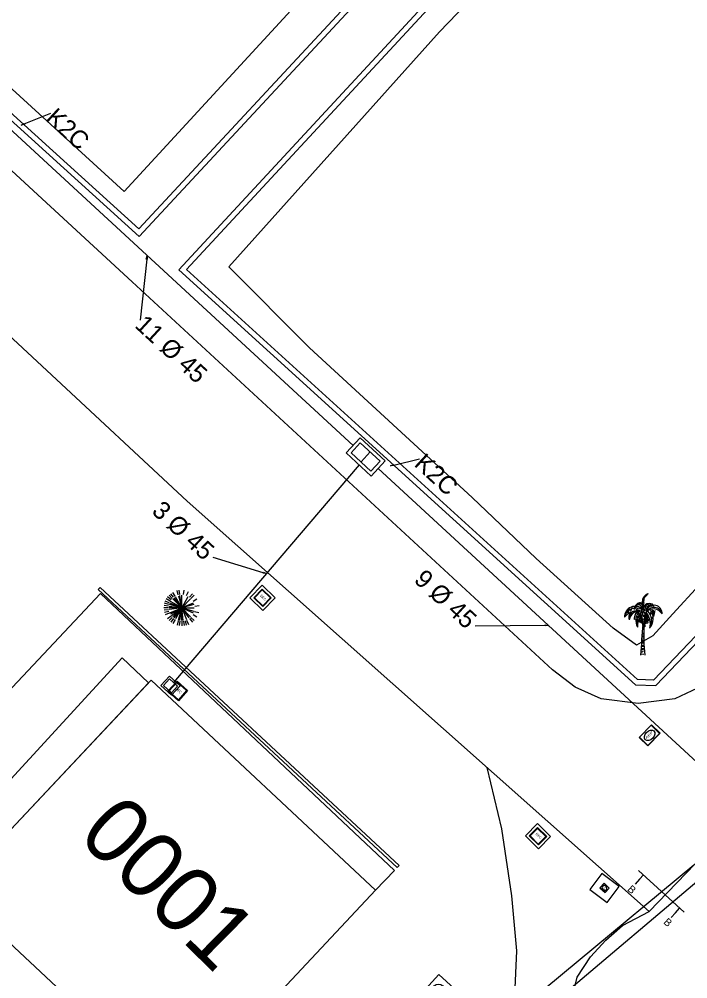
# Model space of a CAD drawing. Extents: x 343997 to 344255, y 298512 to 298767.
# Drawn here: x 344085.4 to 344122.6, y 298618.2 to 298671.5 of the extents above; entities that cross this region are included whole.
import ezdxf

# ---------------------------------------------------------------- set-up
doc = ezdxf.new("R2010")
doc.units = 0
for name, color, linetype in [('Default', 7, 'Continuous'), ('DH_CADRE-CARTOUCHE', 7, 'Continuous'), ('DH_TEXTE', 7, 'Continuous'), ('DIR-Projet VRD1', 7, 'Continuous'), ('EDE - coupe BT', 7, 'Continuous'), ('EDE - VRD - O-DONNEE', 7, 'Continuous'), ('GO_DALLE', 7, 'Continuous'), ('GO_MUR', 7, 'Continuous'), ('O-Projet New VRD', 7, 'Continuous'), ('OPT texte', 7, 'Continuous'), ('OPT VRD', 7, 'Continuous'), ('PC_REBAR', 7, 'Continuous'), ('PS_MID', 7, 'Continuous'), ('PS_PLATE', 7, 'Continuous'), ('RES_EAU', 7, 'Continuous'), ('RES_ELECTRICITE', 7, 'Continuous')]:
    doc.layers.add(name, color=color, linetype=linetype)

# ---------------------------------------------------------------- blocks, each defined once
blk = doc.blocks.new('RES_EAU')
at = {"layer": 'RES_EAU'}
for points in [[(0, 0), (0, 0.1), (0.1, 0.1), (0.1, 0)], [(0.0025, 0.0025), (0.0025, 0.0975), (0.0975, 0.0975), (0.0975, 0.0025)]]:
    blk.add_lwpolyline(points, close=True, dxfattribs=at)
blk.add_circle((0.05, 0.05), 0.035, dxfattribs=at)
blk.add_text('AEP', height=0.02, dxfattribs=at).set_placement((0.0224, 0.0448))
blk = doc.blocks.new('RES_ELECTRICITE')
at = {"layer": 'RES_ELECTRICITE'}
for points in [[(0, 0), (0, 0.1), (0.1, 0.1), (0.1, 0)], [(0.005, 0.005), (0.005, 0.095), (0.095, 0.095), (0.095, 0.005)]]:
    blk.add_lwpolyline(points, close=True, dxfattribs=at)
blk.add_text('EEC', height=0.02, dxfattribs=at).set_placement((0.0237, 0.046))
blk = doc.blocks.new('COCO')
at = {"layer": 'Default'}
for p, q in [((-0.0037, 0.106), (0.0056, 0.1071)), ((0.0058, 0.114), (-0.003, 0.1162)), ((-0.0026, 0.1226), (0.0061, 0.1212)), ((-0.0062, 0.0537), (0.0046, 0.0552)), ((0.0047, 0.0655), (-0.0058, 0.0642)), ((-0.0046, 0.0891), (0.0052, 0.0927)), ((0.0054, 0.0998), (-0.0041, 0.0985)), ((0.0046, 0.0033), (-0.0076, 0.0051)), ((-0.0073, 0.017), (0.0045, 0.0209)), ((0.0045, 0.0292), (-0.007, 0.0288)), ((-0.0068, 0.0371), (0.0045, 0.0374)), ((0.0045, 0.047), (-0.0065, 0.0453))]:
    blk.add_line(p, q, dxfattribs=at)
for points in [[(0.0029, 0.2551), (-0.0016, 0.2896), (0.0002, 0.3125), (0.0059, 0.3241), (0.0173, 0.3348), (0.0189, 0.3356), (0.0282, 0.3415), (0.0266, 0.3373), (0.02, 0.3318), (0.0143, 0.3247), (0.0093, 0.32), (0.0081, 0.3165), (0.0057, 0.3133), (0.0057, 0.3099), (0.006, 0.3037), (0.0039, 0.2989), (0.0039, 0.2944), (0.0049, 0.2877), (0.0037, 0.2841), (0.0013, 0.2736)], [(-0.0487, 0.268), (-0.0386, 0.265)], [(0.0013, 0.2736), (0.0036, 0.2813), (0.0046, 0.2746)], [(0.0196, 0.2687), (0.0323, 0.2715)], [(0.0283, 0.2765), (0.0331, 0.2786)], [(-0.0746, 0.2559), (-0.0864, 0.2483)], [(-0.077, 0.2413), (-0.0836, 0.2333)], [(-0.0607, 0.2534), (-0.0704, 0.2443)], [(-0.0636, 0.2639), (-0.0541, 0.2608)], [(-0.0421, 0.258), (-0.0503, 0.2523)], [(-0.0183, 0.2493), (-0.0348, 0.2417), (-0.0401, 0.2307), (-0.0448, 0.2203), (-0.0471, 0.2086), (-0.0474, 0.2023), (-0.0466, 0.1973), (-0.0455, 0.2054), (-0.0451, 0.2146), (-0.0387, 0.2292), (-0.0351, 0.2354), (-0.0284, 0.2404), (-0.0233, 0.2445), (-0.0012, 0.2495)], [(-0.0256, 0.2553), (-0.0385, 0.2508)], [(-0.0276, 0.2151), (-0.0329, 0.2086)], [(-0.0203, 0.2314), (-0.0274, 0.2258)], [(-0.023, 0.2152), (-0.0237, 0.2043)], [(-0.0161, 0.2218), (-0.0158, 0.2122)], [(-0.004, 0.2247), (-0.0081, 0.2179)], [(0.0015, 0.2414), (-0.0056, 0.2352)], [(0.0022, 0.224), (0.0043, 0.213)], [(0.0081, 0.2404), (0.0106, 0.2299)], [(0.0133, 0.2608), (0.0185, 0.2634)], [(0.0385, 0.237), (0.0469, 0.2254)], [(-0.0321, 0.1997), (-0.0364, 0.19)], [(-0.0059, 0.2024), (-0.0083, 0.1998)], [(-0.0025, 0.2032), (0.0002, 0.1954)], [(0.0473, 0.2115), (0.0509, 0.2012)], [(-0.0055, 0.0716), (0.0048, 0.0717), (0.0049, 0.0787), (-0.0051, 0.0795)]]:
    blk.add_lwpolyline(points, dxfattribs=at)
for centre, radius in [((-0.0187, 0.1897), 0.00384), ((-0.0144, 0.1978), 0.00616), ((-0.0124, 0.1896), 0.00376), ((-0.011, 0.184), 0.00471), ((0.0134, 0.1862), 0.00549), ((0.0208, 0.1822), 0.00626), ((0.0254, 0.1938), 0.00628)]:
    blk.add_circle(centre, radius, dxfattribs=at)
for centre, radius, start, end in [((-0.0427, 0.2113), 0.0595, 43.6121, 181.4625), ((-0.0123, 0.259), 0.0323, 122.3475, 158.7636), ((-0.0199, 0.2618), 0.0238, 4.5218, 154.101), ((-0.0252, 0.2556), 0.0231, 4.2441, 134.2103), ((-0.016, 0.2647), 0.0255, 21.0861, 122.3475), ((0.0376, 0.2508), 0.0372, 113.7681, 175.3309), ((0.0376, 0.2508), 0.0372, 113.7681, 175.3309), ((0.0418, 0.2527), 0.0326, 97.1248, 183.9512), ((0.1025, 0.2053), 0.0958, 126.6858, 153.1664), ((0.0618, 0.2316), 0.0451, 356.1627, 159.0009), ((0.0344, 0.2407), 0.0451, 69.0817, 104.862), ((-0.1005, 0.1577), 0.1786, 37.5668, 40.5156), ((-0.0254, 0.228), 0.0869, 28.4725, 37.0965), ((0.0493, 0.2767), 0.00679, 35.3205, 126.6858), ((-0.0054, 0.2379), 0.0738, 25.8194, 35.3205), ((-0.0291, 0.1543), 0.0918, 76.7389, 142.8025), ((-0.038, 0.1964), 0.0648, 57.9192, 166.6201), ((-0.03, 0.212), 0.0482, 151.1331, 199.5942), ((-0.0196, 0.1874), 0.0565, 78.514, 171.3504), ((-0.032, 0.2055), 0.0433, 119.0834, 188.7621), ((0.0362, 0.1922), 0.0754, 136.7113, 208.8221), ((0.0551, 0.179), 0.0879, 137.733, 194.3716), ((0.0649, 0.1599), 0.0949, 145.5146, 182.4528), ((0.062, 0.2159), 0.0753, 153.0868, 230.1124), ((0.0659, 0.2068), 0.0718, 142.3554, 222.2794), ((-0.0007, 0.2465), 0.00563, 81.7475, 144.3035), ((-0.0189, 0.121), 0.1324, 71.3715, 81.7475), ((0.0294, 0.2595), 0.0256, 198.6765, 199.7627), ((0.0963, 0.1939), 0.09, 143.9866, 203.4288), ((0.0544, 0.1816), 0.0474, 137.1953, 172.8987), ((0.0308, 0.2014), 0.0226, 121.4297, 182.29), ((2.7302, 0.0106), 2.7266, 175.4791, 176.5597), ((0.0311, 0.2152), 0.0219, 141.856, 191.5175), ((0.0404, 0.1878), 0.0354, 125.0585, 146.3893), ((0.0398, 0.2098), 0.0301, 136.4569, 162.0685), ((0.0357, 0.2084), 0.0244, 133.1184, 172.7534), ((-0.0759, 0.1958), 0.0922, 344.8505, 15.8988), ((-0.0404, 0.2045), 0.0619, 329.4666, 26.6793), ((-0.0289, 0.211), 0.0564, 317.8279, 12.3386), ((0.059, 0.2015), 0.0548, 29.5654, 139.3517), ((-0.0543, 0.1744), 0.096, 344.8781, 41.1461), ((-0.0341, 0.19), 0.0828, 46.9767, 50.1231), ((0.0609, 0.2187), 0.0468, 12.1077, 148.3146), ((-0.0157, 0.2027), 0.074, 51.2475, 54.5217), ((-0.0341, 0.19), 0.0828, 334.0687, 41.194), ((-0.0157, 0.2027), 0.074, 315.1472, 39.0239), ((-0.1704, 0.1849), 0.2327, 7.5978, 16.3666), ((-0.0254, 0.228), 0.0869, 350.8883, 14.7063), ((-0.0482, 0.2552), 0.1161, 339.3597, 356.5925), ((-8.5428, 0.7294), 8.5622, 355.11326, 356.26352), ((-0.0279, 0.1637), 0.0281, 2.1499, 36.6325), ((-0.0265, 0.1505), 0.0316, 339.9997, 25.7228), ((0.0199, 0.166), 0.0176, 166.9443, 185.5966), ((0.0372, 0.1847), 0.0277, 133.5956, 173.487), ((0.0808, 0.1542), 0.0777, 142.2358, 156.28), ((0.0242, 0.1964), 0.0147, 110.9727, 165.9756)]:
    blk.add_arc(centre, radius, start, end, dxfattribs=at)
blk.add_ellipse((2.7425, 0.0272), major_axis=(-2.7371, 0.0966), ratio=0.529859, start_param=6.255729, end_param=6.369141, dxfattribs=at)
blk = doc.blocks.new('ARB2')
at = {"layer": 'Default'}
for p, q in [((-0.0575, 0.0453), (-0.0775, 0.0605)), ((-0.0513, 0.0525), (-0.0688, 0.0702)), ((-0.0438, 0.0589), (-0.0588, 0.0786)), ((-0.0356, 0.0642), (-0.0481, 0.0858)), ((-0.0181, 0.0716), (-0.0244, 0.0956)), ((-0.0088, 0.0736), (-0.0119, 0.0983)), ((0.0106, 0.0736), (0.0144, 0.0983)), ((0.0287, 0.0684), (0.0388, 0.0914)), ((0.0456, 0.0589), (0.0612, 0.0786)), ((0.0531, 0.0525), (0.0706, 0.0702)), ((-0.0731, 0), (-0.0981, 0)), ((-0.0725, 0.01), (-0.0969, 0.0133)), ((-0.0706, 0.0195), (-0.0944, 0.0259)), ((-0.0675, 0.0286), (-0.09, 0.0381)), ((-0.0631, 0.0373), (-0.0844, 0.0497)), ((0.065, 0.0373), (0.0862, 0.0497)), ((0.0744, 0.01), (0.0987, 0.0133)), ((-0.0725, -0.01), (-0.0969, -0.0133)), ((-0.0706, -0.0195), (-0.0944, -0.0259)), ((-0.0675, -0.0287), (-0.09, -0.0383)), ((-0.0575, -0.0455), (-0.0775, -0.0605)), ((-0.0513, -0.0527), (-0.0688, -0.0702)), ((0.0531, -0.0527), (0.0706, -0.0702)), ((0.065, -0.0373), (0.0862, -0.0498)), ((0.0725, -0.0195), (0.0963, -0.0259)), ((-0.0438, -0.0591), (-0.0588, -0.0787)), ((-0.0356, -0.0644), (-0.0481, -0.0859)), ((-0.0181, -0.0717), (-0.0244, -0.0956)), ((-0.0088, -0.0737), (-0.0119, -0.0983)), ((0.0013, -0.0741), (0.0013, -0.0989)), ((0.0106, -0.0737), (0.0144, -0.0983)), ((0.02, -0.0717), (0.0263, -0.0956)), ((0.0287, -0.0686), (0.0388, -0.0916)), ((0.0456, -0.0591), (0.0612, -0.0787))]:
    blk.add_line(p, q, dxfattribs=at)
for points in [[(-0.0688, 0.0091), (0.0013, 0), (-0.0338, 0.0608)], [(-0.0419, 0.0556), (0.0013, 0), (-0.0638, 0.0269)], [(-0.0169, 0.0677), (0.0013, 0), (-0.06, 0.035)], [(0.0013, 0.0008), (0.0013, 0), (-0.0081, 0.0695)], [(0.0362, 0.0608), (0.0013, 0), (0.0013, 0.0702)], [(-0.0487, -0.0497), (0.0013, 0), (-0.0694, 0)], [(-0.0638, -0.0269), (0.0013, 0), (-0.0688, -0.0092)], [(-0.0487, 0.0495), (0.0013, 0), (-0.0669, 0.0181)], [(-0.0169, -0.0678), (0.0013, 0), (-0.06, -0.0352)], [(-0.0544, -0.0428), (0.0013, 0), (-0.0338, -0.0608)], [(-0.0081, -0.0695), (0.0013, 0), (-0.0419, -0.0558)], [(0.0013, -0.0702), (0.0013, 0), (0, 0)], [(0.0656, 0.0269), (0.0013, 0), (0.0506, 0.0495)], [(0.0688, 0.0181), (0.0013, 0), (0.0713, 0)], [(0.0438, -0.0558), (0.0013, 0), (0.0656, -0.0269)], [(0.0506, -0.0497), (0.0013, 0), (0.0688, -0.0181)], [(0.01, -0.0695), (0.0013, 0), (0.0281, -0.0648)], [(0.0019, 0), (0.0013, 0), (0.0013, -0.0009)]]:
    blk.add_lwpolyline(points, dxfattribs=at)
blk = doc.blocks.new('_U58')
at = {"layer": 'EDE - VRD - O-DONNEE'}
for points in [[(0.01067, 0.01553), (-0.01067, 0.01553), (-0.01067, 0.00632), (0.01067, 0.00632)], [(-0.01067, 0.00632), (0.01067, 0.00632), (0.01067, 0), (-0.01067, 0)]]:
    blk.add_lwpolyline(points, close=True, dxfattribs=at)
for centre in [(-0.00689, 0.01114), (-0.00013, 0.01114), (0.00664, 0.01114)]:
    blk.add_circle(centre, 0.00225, dxfattribs=at)
blk.add_text('3H4', height=0.0035, dxfattribs=at).set_placement((-0.00426, 0.00143))

msp = doc.modelspace()

# ---------------------------------------------------------------- linework, layer by layer
at = {"layer": 'DH_CADRE-CARTOUCHE'}
for points in [[(344124.372, 298692.186), (344148.812, 298670.333), (344149.478, 298669.504), (344150.054, 298668.628), (344150.475, 298667.688), (344150.721, 298667.085), (344151.432, 298665.306), (344151.673, 298664.395), (344151.676, 298663.909), (344143.5, 298656.169), (344142.683, 298655.44), (344135.602, 298647.623), (344124.992, 298635.682), (344123.722, 298634.656), (344121.833, 298633.77), (344119.792, 298633.516), (344117.727, 298633.77), (344116.3, 298634.425), (344115.03, 298635.389), (344091.665, 298656.941), (344066.817, 298679.859)], [(344079.116, 298659.278), (344094.724, 298644.749), (344120.412, 298621.951), (344137.791, 298639.981), (344144.065, 298646.663), (344154.783, 298657.656), (344157.662, 298660.576), (344158.342, 298661.39), (344163.216, 298666.766), (344163.731, 298667.308), (344164.688, 298668.072), (344165.676, 298668.545), (344166.447, 298668.825), (344167.222, 298669.059), (344168.509, 298669.289), (344169.751, 298669.392), (344170.251, 298669.414), (344170.803, 298669.375), (344172.06, 298669.227), (344173.884, 298668.877), (344175.641, 298668.318)], [(344121.252, 298590.512), (344117.022, 298602.738), (344113.246, 298614.159), (344112.944, 298617.299), (344113.043, 298619.78), (344112.777, 298622.825), (344112.214, 298626.551), (344111.396, 298629.953)], [(344124.087, 298591.493), (344119.864, 298603.699), (344116.2, 298614.781), (344116.04, 298616.133), (344116.105, 298617.106), (344116.408, 298618.318), (344117.143, 298619.443), (344117.987, 298620.373), (344118.918, 298621.174), (344120.412, 298621.951)]]:
    msp.add_lwpolyline(points, dxfattribs=at)
at = {"layer": 'DIR-Projet VRD1'}
for p, q in [((344084.823, 298665.5), (344103.948, 298647.853)), ((344104.282, 298646.765), (344093.973, 298634.686)), ((344105.347, 298646.566), (344126.33, 298627.218)), ((344126.364, 298626.406), (344111.814, 298614.103))]:
    msp.add_line(p, q, dxfattribs=at)
at = {"layer": 'EDE - coupe BT'}
for p, q in [((344119.863, 298623.745), (344120.094, 298623.996)), ((344121.863, 298621.892), (344122.095, 298622.143))]:
    msp.add_line(p, q, dxfattribs=at)
for points in [[(344122.341, 298621.916), (344119.818, 298624.238)], [(344119.863, 298623.745), (344119.62, 298623.481)], [(344121.863, 298621.892), (344121.62, 298621.627)]]:
    msp.add_lwpolyline(points, dxfattribs=at)
at = {"layer": 'GO_DALLE'}
for points in [[(344098.902, 298640.078), (344098.218, 298639.381), (344098.93, 298638.685), (344099.613, 298639.382)], [(344114.202, 298626.837), (344113.528, 298626.157), (344114.246, 298625.445), (344114.921, 298626.125)], [(344117.109, 298623.181), (344118.07, 298622.459), (344118.734, 298623.347), (344117.773, 298624.069)]]:
    msp.add_lwpolyline(points, close=True, dxfattribs=at)
msp.add_lwpolyline([(344105.192, 298623.148), (344106.258, 298624.234), (344089.907, 298639.614), (344077.802, 298626.745), (344080.101, 298624.659)], dxfattribs=at)
at = {"layer": 'GO_MUR'}
msp.add_lwpolyline([(344089.894, 298639.96), (344106.509, 298624.503), (344106.406, 298624.393), (344089.792, 298639.85)], close=True, dxfattribs=at)
at = {"layer": 'O-Projet New VRD'}
msp.add_line((344104.902, 298647.486), (344104.393, 298646.934), dxfattribs=at)
for points in [[(344085.678, 298665.713), (344087.157, 298666.304)], [(344092.482, 298658.194), (344092.118, 298654.801)], [(344106.211, 298646.756), (344107.636, 298647.107)], [(344098.955, 298640.777), (344096.165, 298641.614)], [(344114.617, 298637.849), (344110.736, 298637.803)], [(344093.746, 298635.026), (344094.333, 298634.485), (344093.859, 298633.97), (344093.27, 298634.512), (344093.744, 298635.027)], [(344093.754, 298634.888), (344094.195, 298634.482), (344093.856, 298634.113), (344093.415, 298634.52), (344093.754, 298634.888)]]:
    msp.add_lwpolyline(points, dxfattribs=at)
for points in [[(344085.69, 298665.685), (344085.511, 298665.646), (344085.667, 298665.741)], [(344092.452, 298658.197), (344092.501, 298658.373), (344092.511, 298658.191)], [(344104.338, 298648.276), (344105.736, 298646.989), (344104.957, 298646.143), (344103.559, 298647.43)], [(344104.35, 298647.994), (344105.453, 298646.978), (344104.945, 298646.426), (344103.841, 298647.442)], [(344106.218, 298646.727), (344106.036, 298646.713), (344106.204, 298646.785)], [(344098.964, 298640.806), (344099.127, 298640.725), (344098.946, 298640.748)], [(344114.617, 298637.879), (344114.797, 298637.852), (344114.618, 298637.819)]]:
    msp.add_lwpolyline(points, close=True, dxfattribs=at)
at = {"layer": 'OPT VRD'}
msp.add_lwpolyline([(344122.894, 298624.526), (344110.021, 298613.871)], dxfattribs=at)
at = {"layer": 'PC_REBAR'}
for points in [[(344115.386, 298697.034), (344095.685, 298715.142), (344067.379, 298684.161), (344067.261, 298683.991), (344067.218, 298683.388), (344067.403, 298682.745), (344071.702, 298678.318), (344092.045, 298659.877), (344116.981, 298686.713), (344117.24, 298686.552), (344092.063, 298659.455), (344071.494, 298678.102), (344067.135, 298682.59), (344066.915, 298683.356), (344066.967, 298684.094), (344067.145, 298684.349), (344095.667, 298715.566), (344115.589, 298697.255)], [(344129.915, 298683.811), (344149.954, 298665.484), (344120.649, 298634.816), (344119.758, 298634.843), (344094.693, 298657.614), (344119.626, 298684.533), (344119.467, 298684.803), (344094.267, 298657.595), (344119.638, 298634.546), (344120.774, 298634.512), (344150.383, 298665.499), (344130.117, 298684.033)]]:
    msp.add_lwpolyline(points, close=True, dxfattribs=at)
for points in [[(344091.233, 298661.951), (344078.543, 298673.539), (344067.651, 298683.727), (344070.267, 298686.633), (344094.013, 298711.291), (344094.723, 298711.636), (344095.462, 298711.65), (344096.516, 298711.35), (344098.055, 298710.152), (344102.625, 298705.772), (344106.459, 298702.051), (344111.683, 298696.937), (344113.434, 298695.237), (344113.122, 298693.176), (344113.133, 298690.945), (344113.53, 298689.467), (344114.335, 298687.988), (344114.712, 298687.466), (344091.233, 298661.951)], [(344097.038, 298657.765), (344108.757, 298670.826), (344120.202, 298682.712)], [(344123.173, 298640.08), (344121.715, 298638.486), (344120.611, 298637.277), (344119.699, 298636.759), (344118.394, 298637.704), (344114.121, 298641.565), (344110.576, 298644.947), (344101.52, 298653.263), (344097.038, 298657.765)]]:
    msp.add_lwpolyline(points, dxfattribs=at)
at = {"layer": 'PS_MID'}
msp.add_lwpolyline([(344082.656, 298626.853), (344091.108, 298636.05), (344092.582, 298634.665), (344084.042, 298625.579), (344082.656, 298626.853)], dxfattribs=at)
at = {"layer": 'PS_PLATE'}
msp.add_lwpolyline([(344092.72, 298634.812), (344105.192, 298623.148), (344094.238, 298611.445), (344080.101, 298624.659), (344082.365, 298627.121), (344084.042, 298625.579), (344092.72, 298634.812)], dxfattribs=at)

# ---------------------------------------------------------------- block references
at = {"layer": 'OPT texte', "xscale": 150, "yscale": 150, "rotation": -42.63277399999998}
msp.add_blockref('_U58', (344108.323, 298615.656), dxfattribs=at)
at = {"layer": 'PC_REBAR', "xscale": 10, "yscale": 10}
for name, p in [('ARB2', (344094.411, 298638.824)), ('COCO', (344120.052, 298636.202))]:
    msp.add_blockref(name, p, dxfattribs=at)
at = {"layer": 'RES_EAU'}
for p, xscale, yscale, rotation in [((344120.33, 298631.157), 9.802445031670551, 6.759738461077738, 45.80865), ((344117.666, 298623.279), 3.3801469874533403, -3.9404763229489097, 46.85669999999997)]:
    msp.add_blockref('RES_EAU', p, dxfattribs=dict(at, xscale=xscale, yscale=yscale, rotation=rotation))
at = {"layer": 'RES_ELECTRICITE'}
for p, xscale, yscale, rotation in [((344098.431, 298639.384), 6.95131563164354, 6.7582209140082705, -44.38035000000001), ((344093.66, 298634.202), 7.944417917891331, 7.5292647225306, -42.15743999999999), ((344113.74, 298626.158), 7.11889624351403, 6.575888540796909, -44.753850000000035)]:
    msp.add_blockref('RES_ELECTRICITE', p, dxfattribs=dict(at, xscale=xscale, yscale=yscale, rotation=rotation))

# ---------------------------------------------------------------- texts
at = {"layer": 'DH_TEXTE'}
msp.add_text('0001', height=3.662, rotation=315.3665, dxfattribs=at).set_placement((344088.56, 298626.095))
at = {"layer": 'EDE - coupe BT'}
for p in [(344119.16, 298623.152), (344121.166, 298621.325)]:
    msp.add_text('B', height=0.42, rotation=317.3672, dxfattribs=at).set_placement(p)
at = {"layer": 'O-Projet New VRD'}
for s, p in [('K2C', (344086.808, 298665.946)), ('11 Ø 45', (344091.767, 298654.45)), ('K2C', (344107.287, 298646.749)), ('3 Ø 45', (344092.708, 298644.123)), ('9 Ø 45', (344107.279, 298640.311))]:
    msp.add_text(s, height=1.0003, rotation=317.3672, dxfattribs=at).set_placement(p)

doc.saveas('drawing.dxf')
